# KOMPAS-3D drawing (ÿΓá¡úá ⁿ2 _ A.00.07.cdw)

Views: Спереди 1, Местный разрез 1, Спереди, Проекционный вид 2, Изометрия XYZ 3, Изометрия XYZ, Разрез А-А
Referenced files in C:\Users\s.slezkin\Desktop\Раскатчик арок 2\: Штанга №2 _ A.00.07.m3d, Штанга №2 _ A.00.07.cdw
Referenced files in C:\Program Files (x86)\ASCON\KOMPAS-3D V15\Libs\PartLib\DATA\vault\Methods\Kompas\3D\: PLib_Nut_OST92_900.m3d
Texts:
  Штанга №2
  http://vk.com/sergey_krd
  Гайка М10х1,5-6Н
  ГОСТ 2524-70
  1. Трубы квадратные и гайку М10х1,5-6Н приварить по
  ГОСТ 5264-80;
  2. Штангу изготовить из труб стальных квадратных
  50х50х4 и 40x40x2 ГОСТ 8639-82.
  Гайка М10-6H ГОСТ 2524-70
Dimensions and other numbers on the sheet: 4; 42; 130; 2; 46; 5; 40; 25; 15; 10; 1:1; 1; 0,51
